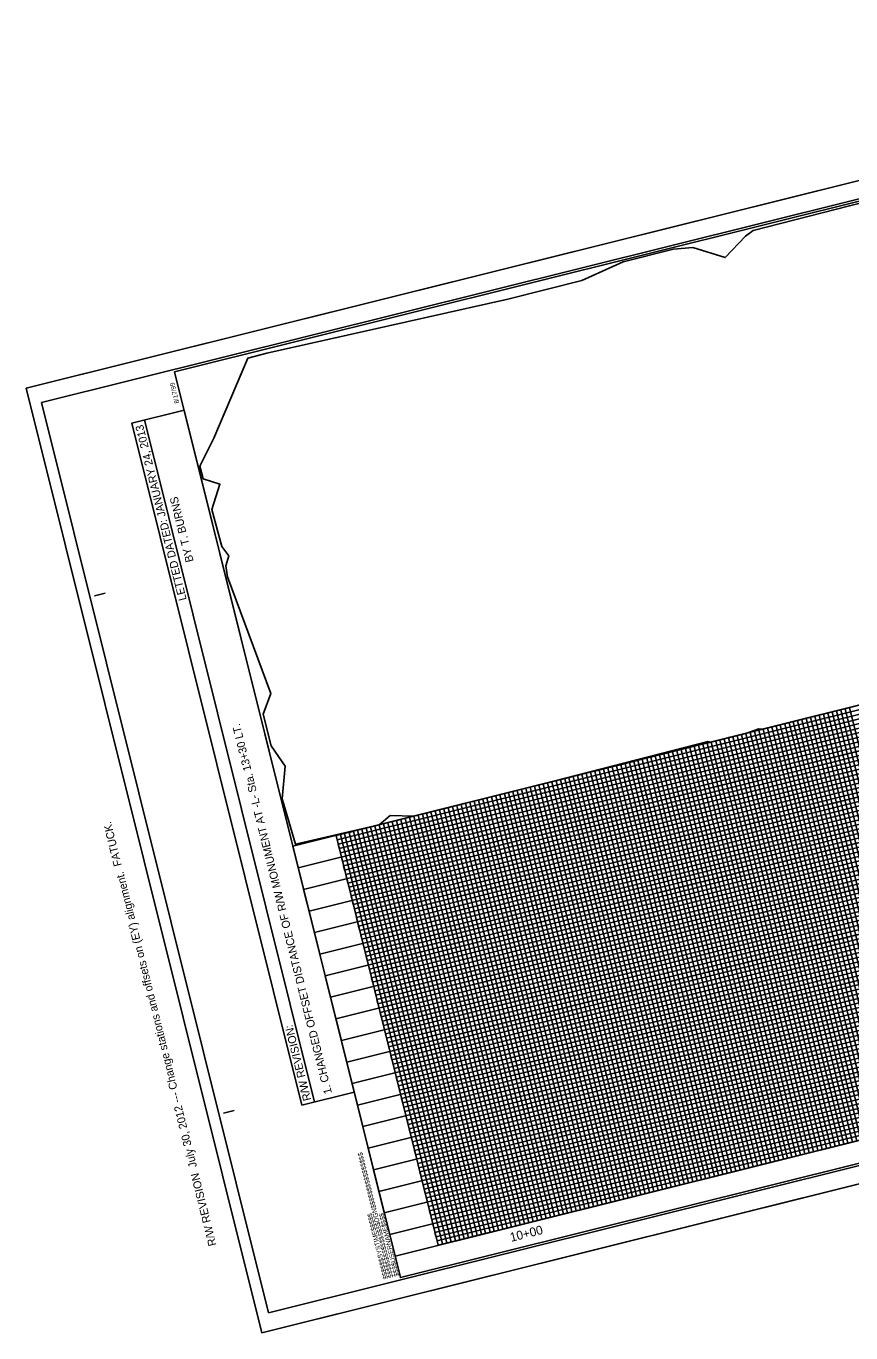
# Model space of a CAD drawing. Extents: x 1030486 to 1032384, y 655714 to 657184.
# Drawn here: x 1030486 to 1031413, y 655714 to 657184 of the extents above; entities that cross this region are included whole.
import ezdxf

# ---------------------------------------------------------------- set-up
doc = ezdxf.new("R2010")
doc.units = 0
for name, color, linetype in [('Exist Vertical Profile Horizontal Axis Label Major', 7, 'Continuous'), ('Sheet Block Revision CELL', 7, 'Continuous'), ('Sheet Block System Information CELL', 7, 'Continuous'), ('Sheet Clip Boundary CELL', 7, 'Continuous'), ('Sheet Cutting Line CELL', 7, 'Continuous'), ('Sheet DOT Grid CELL', 7, 'Continuous'), ('Sheet Layout Plan Border', 7, 'Continuous'), ('Sheet Layout Profile Border Port 2', 7, 'Continuous'), ('Sheet Plan And Profile CELL', 7, 'Continuous'), ('Sheet Plot Border Inside CELL', 7, 'Continuous'), ('Sheet Plot Border Outside CELL', 7, 'Continuous'), ('Sheet Profile Grid Major CELL', 7, 'Continuous'), ('Sheet Profile Grid Middle CELL', 7, 'Continuous'), ('Sheet Profile Grid Minor CELL', 7, 'Continuous')]:
    doc.layers.add(name, color=color, linetype=linetype)

msp = doc.modelspace()

# ---------------------------------------------------------------- linework, layer by layer
at = {"layer": 'Sheet Block Revision CELL'}
msp.add_line((1030809.9, 655973.7), (1030618.7, 656740.9), dxfattribs=at)
msp.add_lwpolyline([(1030795.8, 655970.2), (1030604.6, 656737.4), (1030663.3, 656752), (1030854.6, 655984.9)], close=True, dxfattribs=at)
at = {"layer": 'Sheet Block System Information CELL'}
msp.add_line((1030906.6, 655776.3), (1030906.6, 655776.3), dxfattribs=at)
at = {"layer": 'Sheet Clip Boundary CELL'}
msp.add_lwpolyline([(1031416.3, 656418.7), (1031314.4, 656393.3), (1031309.7, 656393.5), (1031295, 656388.4), (1031256.2, 656378.7), (1031252.1, 656379.3), (1031052.5, 656327.9), (1030921.5, 656295.3), (1030895, 656296.2), (1030882.7, 656285.6), (1030788.4, 656263.7), (1030773.4, 656314.9), (1030777, 656351.7), (1030761.3, 656374.6), (1030752.1, 656410), (1030760.7, 656433.3), (1030712.1, 656564.5), (1030710.2, 656576.7), (1030713.4, 656588), (1030705.5, 656598.6), (1030694.6, 656640.2), (1030703.5, 656668.6), (1030684.8, 656674.8), (1030681, 656688.9), (1030696.6, 656720.6), (1030734.8, 656810.3), (1030756.1, 656815.9), (1031027.3, 656876.9), (1031110.5, 656897.9), (1031156.9, 656918.7), (1031213.6, 656933), (1031235.4, 656934.9), (1031271.8, 656923.6), (1031294.6, 656947.7), (1031303.2, 656954.2), (1031411.6, 656981.9), (1031524, 657010.1)], dxfattribs=at)
at = {"layer": 'Sheet Cutting Line CELL'}
for p, q in [((1032119.1, 657183.9), (1030485.6, 656776.6)), ((1030485.6, 656776.6), (1030750.5, 655714.1)), ((1030750.5, 655714.1), (1032384, 656121.4))]:
    msp.add_line(p, q, dxfattribs=at)
at = {"layer": 'Sheet DOT Grid CELL'}
for p, q in [((1030785.6, 656261.4), (1032241.1, 656624.3)), ((1030797.7, 656212.9), (1032253.2, 656575.8)), ((1030809.8, 656164.4), (1032265.3, 656527.3)), ((1030821.9, 656115.9), (1032277.4, 656478.7)), ((1030834, 656067.3), (1032289.5, 656430.2)), ((1031367.8, 656406.6), (1031482.7, 655945.7)), ((1031319.3, 656394.5), (1031434.2, 655933.6)), ((1030846.1, 656018.8), (1032301.6, 656381.7)), ((1031270.8, 656382.4), (1031385.7, 655921.5)), ((1031222.3, 656370.3), (1031337.2, 655909.4)), ((1031125.2, 656346.1), (1031240.1, 655885.2)), ((1031173.7, 656358.2), (1031288.7, 655897.3)), ((1030858.2, 655970.3), (1032313.7, 656333.2)), ((1031076.7, 656334), (1031191.6, 655873.1)), ((1031028.2, 656321.9), (1031143.1, 655861)), ((1030979.7, 656309.8), (1031094.6, 655848.9)), ((1030931.2, 656297.7), (1031046.1, 655836.8)), ((1030834.1, 656273.5), (1030949.1, 655812.6)), ((1030870.3, 655921.8), (1032325.7, 656284.7)), ((1030882.7, 656285.6), (1030997.6, 655824.7)), ((1030882.4, 655873.3), (1032337.8, 656236.2)), ((1030894.5, 655824.8), (1032349.9, 656187.7))]:
    msp.add_line(p, q, dxfattribs=at)
at = {"layer": 'Sheet Layout Plan Border'}
msp.add_lwpolyline([(1030906.6, 655776.3), (1030785.6, 656261.4), (1031949.9, 656551.7), (1032241.1, 656624.3), (1032362, 656139.1)], close=True, dxfattribs=at)
at = {"layer": 'Sheet Layout Profile Border Port 2'}
msp.add_lwpolyline([(1030834.1, 656273.5), (1032192.6, 656612.2), (1032307.5, 656151.3), (1030949.1, 655812.6)], close=True, dxfattribs=at)
at = {"layer": 'Sheet Plan And Profile CELL'}
for p, q in [((1030562.3, 656543.3), (1030574.4, 656546.3)), ((1032356, 656163.4), (1030900.5, 655800.5)), ((1030707.5, 655961.1), (1030719.6, 655964.1)), ((1030906.6, 655776.3), (1030906.6, 655776.3)), ((1030906.6, 655776.3), (1030906.6, 655776.3)), ((1030906.6, 655776.3), (1030906.6, 655776.3)), ((1030906.6, 655776.3), (1030906.6, 655776.3)), ((1030906.6, 655776.3), (1030906.6, 655776.3))]:
    msp.add_line(p, q, dxfattribs=at)
msp.add_lwpolyline([(1032108, 657158), (1030652.6, 656795.1), (1030906.6, 655776.3), (1032362, 656139.1)], close=True, dxfattribs=at)
at = {"layer": 'Sheet Plot Border Inside CELL'}
msp.add_lwpolyline([(1030758.3, 655736.7), (1032374.8, 656139.7), (1032119.5, 657163.4), (1030503, 656760.4)], close=True, dxfattribs=at)
at = {"layer": 'Sheet Plot Border Outside CELL'}
msp.add_lwpolyline([(1030750.5, 655714.1), (1032384, 656121.4), (1032119.1, 657183.9), (1030485.6, 656776.6)], close=True, dxfattribs=at)
at = {"layer": 'Sheet Profile Grid Major CELL'}
for points in [[(1030785.6, 656261.4), (1032241.1, 656624.3)], [(1032253.2, 656575.8), (1030797.7, 656212.9), (1030809.8, 656164.4), (1032265.3, 656527.3)], [(1032277.4, 656478.7), (1030821.9, 656115.9), (1030834, 656067.3), (1032289.5, 656430.2)], [(1031434.2, 655933.6), (1031319.3, 656394.5), (1031367.8, 656406.6), (1031482.7, 655945.7)], [(1032301.6, 656381.7), (1030846.1, 656018.8), (1030858.2, 655970.3), (1032313.7, 656333.2)], [(1031337.2, 655909.4), (1031222.3, 656370.3), (1031270.8, 656382.4), (1031385.7, 655921.5)], [(1031240.1, 655885.2), (1031125.2, 656346.1), (1031173.7, 656358.2), (1031288.7, 655897.3)], [(1031143.1, 655861), (1031028.2, 656321.9), (1031076.7, 656334), (1031191.6, 655873.1)], [(1031046.1, 655836.8), (1030931.2, 656297.7), (1030979.7, 656309.8), (1031094.6, 655848.9)], [(1030949.1, 655812.6), (1030834.1, 656273.5), (1030882.7, 656285.6), (1030997.6, 655824.7)], [(1032325.7, 656284.7), (1030870.3, 655921.8), (1030882.4, 655873.3), (1032337.8, 656236.2)], [(1030785.6, 656261.4), (1030900.5, 655800.5)], [(1032349.9, 656187.7), (1030894.5, 655824.8)]]:
    msp.add_lwpolyline(points, dxfattribs=at)
at = {"layer": 'Sheet Profile Grid Middle CELL'}
for p, q in [((1030791.7, 656237.1), (1032247.1, 656600)), ((1032259.2, 656551.5), (1030803.8, 656188.6)), ((1030815.9, 656140.1), (1032271.3, 656503)), ((1032283.4, 656454.5), (1030828, 656091.6)), ((1030840.1, 656043.1), (1032295.5, 656406)), ((1032307.6, 656357.5), (1030852.2, 655994.6)), ((1030864.3, 655946.1), (1032319.7, 656308.9)), ((1032331.8, 656260.4), (1030876.4, 655897.5)), ((1030888.4, 655849), (1032343.9, 656211.9)), ((1030803.8, 656188.6), (1030815.9, 656140.1)), ((1030828, 656091.6), (1030840.1, 656043.1)), ((1030852.2, 655994.6), (1030864.3, 655946.1)), ((1030876.4, 655897.5), (1030888.4, 655849))]:
    msp.add_line(p, q, dxfattribs=at)
for points in [[(1031458.5, 655939.6), (1031343.6, 656400.5), (1031392.1, 656412.6), (1031507, 655951.7)], [(1031361.4, 655915.4), (1031246.5, 656376.3), (1031295, 656388.4), (1031409.9, 655927.5)], [(1031264.4, 655891.2), (1031149.5, 656352.1), (1031198, 656364.2), (1031312.9, 655903.3)], [(1031167.4, 655867), (1031052.5, 656327.9), (1031101, 656340), (1031215.9, 655879.1)], [(1031070.3, 655842.9), (1030955.4, 656303.7), (1031003.9, 656315.8), (1031118.9, 655854.9)], [(1030973.3, 655818.7), (1030858.4, 656279.6), (1030906.9, 656291.6), (1031021.8, 655830.8)]]:
    msp.add_lwpolyline(points, dxfattribs=at)
at = {"layer": 'Sheet Profile Grid Minor CELL'}
for points in [[(1032193.8, 656607.3), (1030835.4, 656268.7)], [(1032196.2, 656597.6), (1030837.8, 656258.9), (1030836.6, 656263.8), (1032195, 656602.5)], [(1032199.8, 656583.1), (1030841.4, 656244.4), (1030840.2, 656249.2), (1030839, 656254.1), (1032197.4, 656592.8)], [(1032202.2, 656573.4), (1030843.8, 656234.7), (1030842.6, 656239.5), (1032201, 656578.2)], [(1032205.9, 656558.8), (1030847.5, 656220.1), (1030846.2, 656225), (1030845, 656229.8), (1032203.4, 656568.5)], [(1032208.3, 656549.1), (1030849.9, 656210.4), (1030848.7, 656215.3), (1032207.1, 656554)], [(1032211.9, 656534.6), (1030853.5, 656195.9), (1030852.3, 656200.7), (1030851.1, 656205.6), (1032209.5, 656544.3)], [(1032214.3, 656524.9), (1030855.9, 656186.2), (1030854.7, 656191), (1032213.1, 656529.7)], [(1030859.5, 656171.6), (1030858.3, 656176.5), (1030857.1, 656181.3), (1032215.5, 656520)], [(1032219.2, 656505.5), (1030860.8, 656166.8), (1030859.5, 656171.6), (1032218, 656510.3)], [(1032221.6, 656495.8), (1030863.2, 656157.1), (1030862, 656161.9), (1032220.4, 656500.6)], [(1032225.2, 656481.2), (1030866.8, 656142.5), (1030865.6, 656147.4), (1032224, 656486.1)], [(1032227.6, 656471.5), (1030869.2, 656132.8), (1030868, 656137.7), (1032226.4, 656476.4)], [(1032231.3, 656456.9), (1030872.9, 656118.3), (1030871.6, 656123.1), (1032230.1, 656461.8)], [(1032233.7, 656447.2), (1030875.3, 656108.6), (1030874.1, 656113.4), (1032232.5, 656452.1)], [(1032237.3, 656432.7), (1030878.9, 656094), (1030877.7, 656098.8), (1032236.1, 656437.5)], [(1032239.7, 656423), (1030881.3, 656084.3), (1030880.1, 656089.1), (1032238.5, 656427.8)], [(1032243.4, 656408.4), (1030884.9, 656069.7), (1030883.7, 656074.6), (1032242.2, 656413.3)], [(1031473, 655943.3), (1031358.1, 656404.1), (1031363, 656405.4), (1031477.9, 655944.5)], [(1031487.6, 655946.9), (1031372.7, 656407.8), (1031377.5, 656409), (1031492.4, 655948.1)], [(1031497.3, 655949.3), (1031382.4, 656410.2), (1031387.2, 656411.4), (1031502.1, 655950.5)], [(1031511.8, 655952.9), (1031396.9, 656413.8), (1031401.8, 656415), (1031516.7, 655954.1)], [(1031521.5, 655955.3), (1031406.6, 656416.2), (1031411.5, 656417.4), (1031526.4, 655956.6)], [(1032245.8, 656398.7), (1030887.4, 656060), (1030886.2, 656064.9), (1032244.6, 656403.6)], [(1031414.8, 655928.7), (1031299.9, 656389.6), (1031304.7, 656390.8), (1031419.7, 655929.9)], [(1031424.5, 655931.2), (1031309.6, 656392), (1031314.4, 656393.3), (1031429.4, 655932.4)], [(1031439.1, 655934.8), (1031324.1, 656395.7), (1031329, 656396.9), (1031443.9, 655936)], [(1031448.8, 655937.2), (1031333.8, 656398.1), (1031338.7, 656399.3), (1031453.6, 655938.4)], [(1031463.3, 655940.8), (1031348.4, 656401.7), (1031353.3, 656402.9), (1031468.2, 655942)], [(1032249.4, 656384.2), (1030891, 656045.5), (1030889.8, 656050.3), (1032248.2, 656389)], [(1032251.8, 656374.5), (1030893.4, 656035.8), (1030892.2, 656040.6), (1032250.6, 656379.3)], [(1031366.3, 655916.6), (1031251.4, 656377.5), (1031256.2, 656378.7), (1031371.1, 655917.8)], [(1031376, 655919.1), (1031261.1, 656379.9), (1031265.9, 656381.2), (1031380.8, 655920.3)], [(1031390.5, 655922.7), (1031275.6, 656383.6), (1031280.5, 656384.8), (1031395.4, 655923.9)], [(1031400.2, 655925.1), (1031285.3, 656386), (1031290.2, 656387.2), (1031405.1, 655926.3)], [(1032255.5, 656359.9), (1030897, 656021.2), (1030895.8, 656026.1), (1032254.2, 656364.8)], [(1031303.2, 655900.9), (1031188.3, 656361.8), (1031193.2, 656363), (1031308.1, 655902.1)], [(1031317.8, 655904.5), (1031202.9, 656365.4), (1031207.7, 656366.6), (1031322.6, 655905.8)], [(1031327.5, 655907), (1031212.6, 656367.9), (1031217.4, 656369.1), (1031332.3, 655908.2)], [(1031342, 655910.6), (1031227.1, 656371.5), (1031232, 656372.7), (1031346.9, 655911.8)], [(1031351.7, 655913), (1031236.8, 656373.9), (1031241.7, 656375.1), (1031356.6, 655914.2)], [(1032257.9, 656350.2), (1030899.5, 656011.5), (1030898.3, 656016.4), (1032256.7, 656355.1)], [(1031245, 655886.4), (1031130.1, 656347.3), (1031134.9, 656348.5), (1031249.8, 655887.6)], [(1031254.7, 655888.8), (1031139.8, 656349.7), (1031144.6, 656350.9), (1031259.6, 655890)], [(1031269.3, 655892.4), (1031154.3, 656353.3), (1031159.2, 656354.5), (1031274.1, 655893.7)], [(1031279, 655894.9), (1031164, 656355.8), (1031168.9, 656357), (1031283.8, 655896.1)], [(1031293.5, 655898.5), (1031178.6, 656359.4), (1031183.5, 656360.6), (1031298.4, 655899.7)], [(1032261.5, 656335.7), (1030903.1, 655997), (1030901.9, 656001.8), (1032260.3, 656340.5)], [(1031181.9, 655870.7), (1031067, 656331.6), (1031071.9, 656332.8), (1031186.8, 655871.9)], [(1031196.5, 655874.3), (1031081.6, 656335.2), (1031086.4, 656336.4), (1031201.3, 655875.5)], [(1031206.2, 655876.7), (1031091.3, 656337.6), (1031096.1, 656338.8), (1031211, 655877.9)], [(1031220.7, 655880.4), (1031105.8, 656341.2), (1031110.7, 656342.5), (1031225.6, 655881.6)], [(1031230.4, 655882.8), (1031115.5, 656343.7), (1031120.4, 656344.9), (1031235.3, 655884)], [(1032263.9, 656326), (1030905.5, 655987.3), (1030904.3, 655992.1), (1032262.7, 656330.8)], [(1031123.7, 655856.2), (1031008.8, 656317), (1031013.7, 656318.3), (1031128.6, 655857.4)], [(1031133.4, 655858.6), (1031018.5, 656319.5), (1031023.4, 656320.7), (1031138.3, 655859.8)], [(1031148, 655862.2), (1031033.1, 656323.1), (1031037.9, 656324.3), (1031152.8, 655863.4)], [(1031157.7, 655864.6), (1031042.8, 656325.5), (1031047.6, 656326.7), (1031162.5, 655865.8)], [(1031172.2, 655868.3), (1031057.3, 656329.1), (1031062.2, 656330.4), (1031177.1, 655869.5)], [(1032267.6, 656311.4), (1030909.1, 655972.7), (1030907.9, 655977.6), (1032266.3, 656316.3)], [(1032270, 656301.7), (1030911.6, 655963), (1030910.4, 655967.9), (1032268.8, 656306.6)], [(1031060.6, 655840.4), (1030945.7, 656301.3), (1030950.6, 656302.5), (1031065.5, 655841.6)], [(1031075.2, 655844.1), (1030960.3, 656305), (1030965.1, 656306.2), (1031080, 655845.3)], [(1031084.9, 655846.5), (1030970, 656307.4), (1030974.8, 656308.6), (1031089.8, 655847.7)], [(1031099.5, 655850.1), (1030984.5, 656311), (1030989.4, 656312.2), (1031104.3, 655851.3)], [(1031109.2, 655852.5), (1030994.2, 656313.4), (1030999.1, 656314.6), (1031114, 655853.7)], [(1031002.4, 655825.9), (1030887.5, 656286.8), (1030892.4, 656288), (1031007.3, 655827.1)], [(1031012.1, 655828.3), (1030897.2, 656289.2), (1030902.1, 656290.4), (1031017, 655829.5)], [(1031026.7, 655832), (1030911.8, 656292.9), (1030916.6, 656294.1), (1031031.5, 655833.2)], [(1032273.6, 656287.1), (1030915.2, 655948.5), (1030914, 655953.3), (1032272.4, 656292)], [(1031036.4, 655834.4), (1030921.5, 656295.3), (1030926.3, 656296.5), (1031041.2, 655835.6)], [(1031050.9, 655838), (1030936, 656298.9), (1030940.9, 656300.1), (1031055.8, 655839.2)], [(1030953.9, 655813.8), (1030839, 656274.7), (1030843.8, 656275.9), (1030958.8, 655815)], [(1030963.6, 655816.2), (1030848.7, 656277.1), (1030853.6, 656278.3), (1030968.5, 655817.5)], [(1030978.2, 655819.9), (1030863.3, 656280.8), (1030868.1, 656282), (1030983, 655821.1)], [(1030987.9, 655822.3), (1030873, 656283.2), (1030877.8, 656284.4), (1030992.7, 655823.5)], [(1032276, 656277.4), (1030917.6, 655938.8), (1030916.4, 655943.6), (1032274.8, 656282.3)], [(1032279.7, 656262.9), (1030921.2, 655924.2), (1030920, 655929), (1032278.4, 656267.7)], [(1032282.1, 656253.2), (1030923.7, 655914.5), (1030922.4, 655919.3), (1032280.9, 656258)], [(1032285.7, 656238.6), (1030927.3, 655899.9), (1030926.1, 655904.8), (1032284.5, 656243.5)], [(1032288.1, 656228.9), (1030929.7, 655890.2), (1030928.5, 655895.1), (1032286.9, 656233.8)], [(1030933.3, 655875.7), (1030932.1, 655880.5), (1032290.5, 656219.2)], [(1030947.8, 655817.5), (1032306.3, 656156.2), (1032305.1, 656161), (1030946.6, 655822.3), (1030945.4, 655827.2), (1032303.8, 656165.9), (1032302.6, 656170.7), (1030944.2, 655832), (1030943, 655836.9), (1030941.8, 655841.7), (1032300.2, 656180.4), (1032299, 656185.3), (1030940.6, 655846.6), (1030939.4, 655851.4), (1032297.8, 656190.1), (1032296.6, 656195), (1030938.2, 655856.3), (1030937, 655861.1), (1030935.8, 655866), (1032294.2, 656204.7), (1032293, 656209.5), (1030934.5, 655870.8), (1030933.3, 655875.7), (1032291.7, 656214.4)]]:
    msp.add_lwpolyline(points, dxfattribs=at)

# ---------------------------------------------------------------- texts
at = {"layer": 'Exist Vertical Profile Horizontal Axis Label Major'}
msp.add_text('10+00', height=10, rotation=14, dxfattribs=at).set_placement((1031031.1, 655816.5))
at = {"layer": 'Sheet Block Revision CELL'}
for s, p in [('LETTED DATED: JANUARY 24, 2013', (1030666.2, 656538.9)), ('            BY T. BURNS', (1030683.7, 656543.2)), ('1. CHANGED OFFSET DISTANCE OF R/W MONUMENT AT -L- Sta. 13+30 LT.', (1030829.6, 655984)), ('R/W REVISION  July 30, 2012 --- Change stations and offsets on (EY) alignment.  FATUCK.', (1030699.7, 655813)), ('R/W REVISION:', (1030806.2, 655976.3))]:
    msp.add_text(s, height=9, rotation=104, dxfattribs=at).set_placement(p)
at = {"layer": 'Sheet Block System Information CELL'}
for s, p in [('$$$$$$$$$$$$$$$$DGN$$$$$$$$$$$$$$$$', (1030898.6, 655776.7)), ('$$$$$$SYSTIME$$$$$', (1030892.7, 655775.2)), ('$$$$USERNAME$$$$', (1030905, 655778.3))]:
    msp.add_text(s, height=5.25, rotation=104, dxfattribs=at).set_placement(p)
at = {"layer": 'Sheet Plan And Profile CELL'}
msp.add_text('8/17/99', height=5.25, rotation=104, dxfattribs=at).set_placement((1030657.9, 656760.1))

doc.saveas('drawing.dxf')
